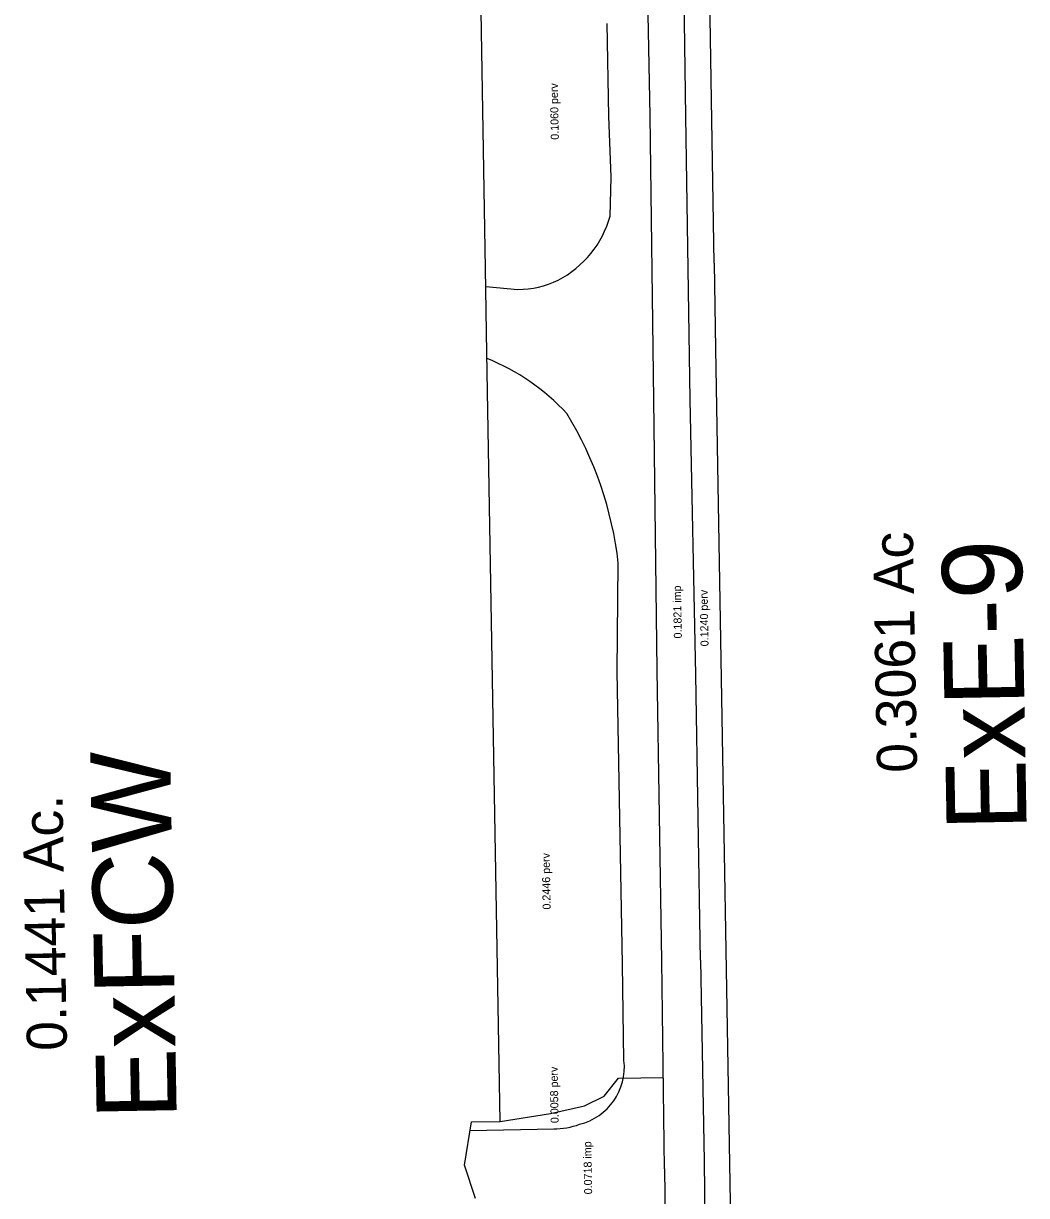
# Model space of a CAD drawing. Extents: x 925564 to 926134, y 853260 to 858402.
# Drawn here: x 925567.9 to 925919, y 856384.4 to 856794.5 of the extents above; entities that cross this region are included whole.
import ezdxf

# ---------------------------------------------------------------- set-up
doc = ezdxf.new("R2010")
doc.units = 0
for name, color, linetype in [('DrainDivides01', 7, 'Continuous'), ('PavtMisc_ep', 7, 'Continuous'), ('TextLabel', 7, 'Continuous')]:
    doc.layers.add(name, color=color, linetype=linetype)

msp = doc.modelspace()

# ---------------------------------------------------------------- linework, layer by layer
at = {"layer": 'DrainDivides01'}
for p, q in [((925809.63, 856710.62), (925801.78, 857180.29)), ((925787.22, 856762.22), (925785.29, 856861.65)), ((925788.53, 856662.87), (925787.22, 856762.22)), ((925809.63, 856710.62), (925810.15, 856680.63)), ((925810.15, 856680.63), (925821.34, 856022.48)), ((925789.71, 856568.18), (925788.53, 856662.87)), ((925791.29, 856466.48), (925789.71, 856568.18)), ((925792.29, 856393.71), (925791.29, 856466.48)), ((925792.29, 856393.71), (925792.52, 856367.9))]:
    msp.add_line(p, q, dxfattribs=at)
for points in [[(925724.71, 856410.17), (925734.71, 856410.34), (925730.14, 856679.29), (925729.65, 856708.82), (925726.87, 856874.9), (925716.87, 856874.74), (925713.51, 857076.08), (925713.01, 857106.07), (925708.61, 857369.25)], [(925734.71, 856410.34), (925752.36, 856413.13), (925764.25, 856415.78), (925771.13, 856419.18), (925776.12, 856425.44), (925791.85, 856425.65)], [(925726.14, 856383.31), (925722.25, 856395), (925724.71, 856410.17)]]:
    msp.add_lwpolyline(points, dxfattribs=at)
at = {"layer": 'PavtMisc_ep'}
for p, q in [((925799.77, 856761.9), (925798.18, 856862.33)), ((925772.83, 856762.08), (925772.2, 856794.52)), ((925773.57, 856740.69), (925772.83, 856762.08)), ((925801.26, 856662.97), (925799.77, 856761.9)), ((925773.23, 856727.1), (925773.57, 856740.69)), ((925729.75, 856702.5), (925740.94, 856701.45)), ((925803.21, 856566.63), (925801.26, 856662.97)), ((925775.72, 856567.76), (925776.09, 856605.66)), ((925777.51, 856465.36), (925775.72, 856567.76)), ((925804.84, 856466.73), (925803.21, 856566.63)), ((925804.84, 856466.73), (925806.15, 856396.39)), ((925778.08, 856431.65), (925777.51, 856465.36)), ((925724.22, 856407.13), (925753.48, 856407.69)), ((925806.15, 856396.39), (925806.47, 856368.23))]:
    msp.add_line(p, q, dxfattribs=at)
for centre, major_axis, ratio, start_param, end_param in [((925738.42, 856736.79), (35.14, 8.42), 0.999773, 4.955607, 5.776544), ((925740.9, 856733.67), (1.57, 32.19), 0.999929, 3.191432, 3.644999), ((925700.01, 856603.7), (-78.5, -12.94), 0.999854, 3.730261, 4.160139), ((925648.4, 856591.01), (4.45, -128.61), 0.998728, 1.650317, 2.08414), ((925757.63, 856429.32), (17.87, -10.22), 0.999798, 5.471014, 6.916497), ((925753.07, 856435.86), (-7.78, -27.08), 0.999582, 0.29445, 0.621781)]:
    msp.add_ellipse(centre, major_axis=major_axis, ratio=ratio, start_param=start_param, end_param=end_param, dxfattribs=at)

# ---------------------------------------------------------------- texts
at = {"layer": 'TextLabel'}
for s, height, p in [('0.1060 perv', 2.8, (925755.28, 856753.85)), ('0.3061 Ac', 14, (925880.68, 856532.45)), ('ExE-9', 28, (925919.02, 856512.17)), ('0.1821 imp', 2.8, (925798.34, 856579.34)), ('0.1240 perv', 2.8, (925807.69, 856576.59)), ('ExFCW', 28, (925621.57, 856411.21)), ('0.1441 Ac.', 14, (925583.16, 856435.15)), ('0.2446 perv', 2.8, (925752.43, 856484.49)), ('0.0058 perv', 2.8, (925755.22, 856409.74)), ('0.0718 imp', 2.8, (925766.96, 856384.85))]:
    msp.add_text(s, height=height, rotation=91.0261, dxfattribs=at).set_placement(p)

doc.saveas('drawing.dxf')
